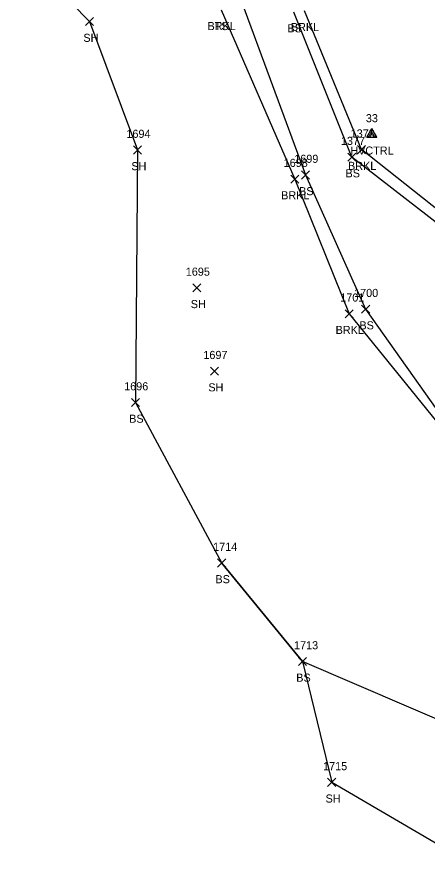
# Model space of a CAD drawing. Extents: x 1754529 to 1755810, y 621660 to 624656.
# Drawn here: x 1754926.3 to 1755027.6, y 623891.6 to 624099.9 of the extents above; entities that cross this region are included whole.
import ezdxf

# ---------------------------------------------------------------- set-up
doc = ezdxf.new("R2010")
doc.units = 0
for name, color, linetype in [('C_A', 7, 'Continuous'), ('C_I', 7, 'Continuous'), ('CPSM', 7, 'Continuous'), ('L_A', 7, 'Continuous'), ('L_I', 7, 'Continuous'), ('L_TIC', 7, 'Continuous'), ('LAWE', 7, 'Continuous'), ('LELB', 7, 'Continuous'), ('LSOGP', 7, 'Continuous')]:
    doc.layers.add(name, color=color, linetype=linetype)

msp = doc.modelspace()

# ---------------------------------------------------------------- linework, layer by layer
at = {"layer": 'CPSM'}
for p, q in [((1755012.73, 624070.12), (1755013.98, 624072.29)), ((1755015.23, 624070.12), (1755013.98, 624072.29)), ((1755013.98, 624070.84), (1755013.98, 624072.29)), ((1755012.73, 624070.12), (1755013.98, 624070.84)), ((1755012.73, 624070.12), (1755015.23, 624070.12)), ((1755013.98, 624070.84), (1755013.98, 624070.84)), ((1755013.98, 624070.84), (1755015.23, 624070.12))]:
    msp.add_line(p, q, dxfattribs=at)
at = {"layer": 'L_TIC'}
for points in [[(1754943.28, 624097.68), (1754945.28, 624099.68)], [(1754945.28, 624097.68), (1754943.28, 624099.68)], [(1754955.13, 624065.98), (1754957.13, 624067.98)], [(1754957.13, 624065.98), (1754955.13, 624067.98)], [(1755010.46, 624066.07), (1755012.46, 624068.07)], [(1755012.46, 624066.07), (1755010.46, 624068.07)], [(1755008.04, 624064.23), (1755010.04, 624066.23)], [(1755010.04, 624064.23), (1755008.04, 624066.23)], [(1754996.58, 624059.81), (1754998.58, 624061.81)], [(1754998.58, 624059.81), (1754996.58, 624061.81)], [(1754993.95, 624058.8), (1754995.95, 624060.8)], [(1754995.95, 624058.8), (1754993.95, 624060.8)], [(1754969.79, 624031.94), (1754971.79, 624033.94)], [(1754971.79, 624031.94), (1754969.79, 624033.94)], [(1755011.46, 624026.69), (1755013.46, 624028.69)], [(1755013.46, 624026.69), (1755011.46, 624028.69)], [(1755007.39, 624025.55), (1755009.39, 624027.55)], [(1755009.39, 624025.55), (1755007.39, 624027.55)], [(1754974.13, 624011.38), (1754976.13, 624013.38)], [(1754976.13, 624011.38), (1754974.13, 624013.38)], [(1754954.64, 624003.64), (1754956.64, 624005.64)], [(1754956.64, 624003.64), (1754954.64, 624005.64)], [(1754975.92, 623964.01), (1754977.92, 623966.01)], [(1754977.92, 623964.01), (1754975.92, 623966.01)], [(1754975.92, 623964.01), (1754977.92, 623966.01)], [(1754977.92, 623964.01), (1754975.92, 623966.01)], [(1754995.89, 623939.7), (1754997.89, 623941.7)], [(1754997.89, 623939.7), (1754995.89, 623941.7)], [(1755003.07, 623909.86), (1755005.07, 623911.86)], [(1755005.07, 623909.86), (1755003.07, 623911.86)]]:
    msp.add_lwpolyline(points, dxfattribs=at)
at = {"layer": 'LAWE'}
for points in [[(1754976.77, 624101.58), (1754994.95, 624059.8), (1755008.39, 624026.55), (1755031, 623998.61)], [(1755043.94, 624041.32), (1755011.46, 624067.07), (1754997.35, 624101.33)]]:
    msp.add_lwpolyline(points, dxfattribs=at)
at = {"layer": 'LELB'}
for points in [[(1754981.29, 624105.08), (1754997.58, 624060.81), (1755012.46, 624027.69), (1755032.85, 623998.91)], [(1755041.22, 624040.25), (1755009.04, 624065.23), (1754994.73, 624101.02)], [(1754955.64, 624004.64), (1754976.92, 623965.01)], [(1755049.82, 623913.03), (1755036.51, 623923.62), (1754996.89, 623940.7), (1754976.92, 623965.01)]]:
    msp.add_lwpolyline(points, dxfattribs=at)
at = {"layer": 'LSOGP'}
msp.add_lwpolyline([(1754926.35, 624117.08), (1754944.28, 624098.68), (1754956.13, 624066.98), (1754955.64, 624004.64), (1754976.92, 623965.01), (1754996.89, 623940.7), (1755004.07, 623910.86), (1755037.03, 623891.65)], dxfattribs=at)

# ---------------------------------------------------------------- texts
at = {"layer": 'C_A'}
msp.add_text('HVCTRL', height=2, dxfattribs=at).set_placement((1755008.67, 624065.84))
at = {"layer": 'C_I'}
msp.add_text('33', height=2, dxfattribs=at).set_placement((1755012.51, 624073.84))
at = {"layer": 'L_A'}
for s, p in [('BRKL', (1754973.42, 624096.58)), ('TS', (1754975.18, 624096.58)), ('BS', (1754993.18, 624096.02)), ('BRKL', (1754994, 624096.33)), ('SH', (1754942.77, 624093.68)), ('SH', (1754954.61, 624061.98)), ('BRKL', (1755008.1, 624062.07)), ('BS', (1755007.48, 624060.23)), ('BS', (1754996.02, 624055.81)), ('BRKL', (1754991.6, 624054.8)), ('SH', (1754969.28, 624027.94)), ('BS', (1755010.91, 624022.69)), ('BRKL', (1755005.04, 624021.55)), ('SH', (1754973.62, 624007.38)), ('BS', (1754954.08, 623999.64)), ('BS', (1754975.37, 623960.01)), ('BS', (1754975.37, 623960.01)), ('BS', (1754995.33, 623935.7)), ('SH', (1755002.56, 623905.86))]:
    msp.add_text(s, height=2, dxfattribs=at).set_placement(p)
at = {"layer": 'L_I'}
for s, p in [('1694', (1754953.39, 624069.98)), ('1378', (1755008.76, 624070.07)), ('1377', (1755006.35, 624068.23)), ('1699', (1754994.83, 624063.81)), ('1698', (1754992.21, 624062.8)), ('1695', (1754968.05, 624035.94)), ('1700', (1755009.61, 624030.69)), ('1701', (1755006.19, 624029.55)), ('1697', (1754972.39, 624015.38)), ('1696', (1754952.84, 624007.64)), ('1714', (1754974.8, 623968.01)), ('1714', (1754974.8, 623968.01)), ('1713', (1754994.77, 623943.7)), ('1715', (1755001.95, 623913.86))]:
    msp.add_text(s, height=2, dxfattribs=at).set_placement(p)

doc.saveas('drawing.dxf')
